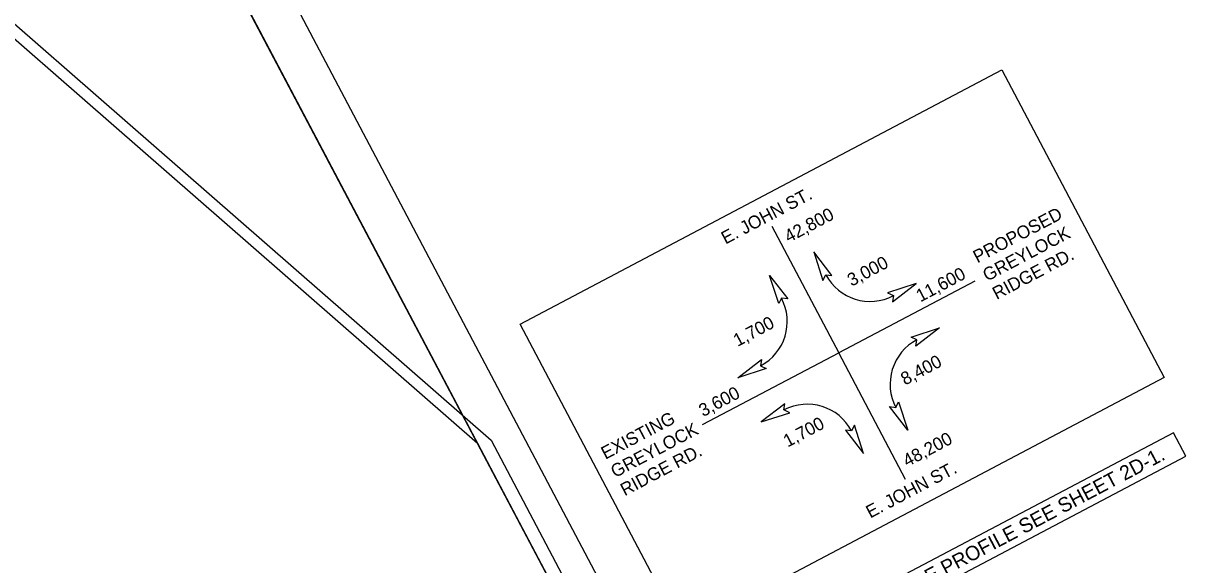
# Model space of a CAD drawing. Extents: x 1487051 to 1489241, y 497582 to 499399.
# Drawn here: x 1488789 to 1489240.5, y 498446.4 to 498656.8 of the extents above; entities that cross this region are included whole.
import ezdxf

# ---------------------------------------------------------------- set-up
doc = ezdxf.new("R2010")
doc.units = 0
for name, color, linetype in [('COGO Default Point Elevation', 7, 'Continuous'), ('Exist DTM Regular Point Cogo Elevation', 7, 'Continuous'), ('Exist Other Culture Sign Post Cogo Comment', 7, 'Continuous'), ('Exist Other Culture Sign Post Cogo Number', 7, 'Continuous'), ('Exist Roads EOP Cogo Point CELL', 7, 'Continuous'), ('Exist Structure Minor Pipes RCP 15 Inch Cogo Comment', 7, 'Continuous'), ('Exist Vegetation Woods Line Cogo Elevation', 7, 'Continuous')]:
    doc.layers.add(name, color=color, linetype=linetype)

msp = doc.modelspace()

# ---------------------------------------------------------------- linework, layer by layer
at = {"layer": 'Exist DTM Regular Point Cogo Elevation'}
for points in [[(1487208.66, 498608.09), (1488222.07, 499143.23), (1488965.37, 498493.68), (1489025.39, 498380), (1487698.94, 497679.61)], [(1487208.66, 498608.09), (1488222.07, 499143.23), (1488965.37, 498493.68), (1489025.39, 498380), (1487698.94, 497679.61)], [(1487214.01, 498609.18), (1488227.42, 499144.32), (1488970.72, 498494.78), (1489030.74, 498381.1), (1487704.3, 497680.71)]]:
    msp.add_lwpolyline(points, close=True, dxfattribs=at)
at = {"layer": 'Exist Other Culture Sign Post Cogo Comment'}
msp.add_lwpolyline([(1488264.23, 499106.38), (1488223.12, 499143.79), (1487208.65, 498608.11), (1487698.94, 497679.61), (1489025.4, 498380.01), (1488871.95, 498670.61), (1488744.3, 498686.86)], close=True, dxfattribs=at)
at = {"layer": 'Exist Other Culture Sign Post Cogo Number'}
for p in [(1489079.72, 498577.99), (1489158.54, 498556.66), (1489052.88, 498500.87), (1489131.7, 498479.55)]:
    msp.add_line(p, (1489105.71, 498528.77), dxfattribs=at)
for points in [[(1489103.08, 498558.78), (1489096.02, 498567.94), (1489099.58, 498556.87), (1489100.69, 498559.1)], [(1489082.41, 498547.87), (1489078.83, 498558.86), (1489085.97, 498549.68), (1489083.5, 498550.02)], [(1489126.65, 498548.6), (1489135.81, 498555.65), (1489124.73, 498552.09), (1489126.96, 498550.98)], [(1489133.9, 498534.87), (1489144.89, 498538.46), (1489135.7, 498531.32), (1489136.04, 498533.79)], [(1489077.53, 498522.66), (1489066.54, 498519.08), (1489075.72, 498526.22), (1489075.38, 498523.75)], [(1489129.01, 498509.66), (1489132.6, 498498.67), (1489125.46, 498507.86), (1489127.93, 498507.51)], [(1489084.77, 498508.94), (1489075.62, 498501.88), (1489086.69, 498505.44), (1489084.46, 498506.55)], [(1489108.35, 498498.75), (1489115.4, 498489.59), (1489111.84, 498500.67), (1489110.73, 498498.44)]]:
    msp.add_lwpolyline(points, close=True, dxfattribs=at)
for centre, start, end in [((1489117.89, 498568.18), 207.8351, 297.8351), ((1489066.3, 498540.94), 297.8351, 27.8351), ((1489145.12, 498516.59), 117.8351, 207.8351), ((1489093.54, 498489.36), 27.8351, 117.8351)]:
    msp.add_arc(centre, 19.44, start, end, dxfattribs=at)
at = {"layer": 'Exist Roads EOP Cogo Point CELL'}
msp.add_lwpolyline([(1487562.23, 497581.96), (1489050.94, 498368.04), (1488539.66, 499336.34), (1487050.94, 498550.27)], close=True, dxfattribs=at)
at = {"layer": 'Exist Structure Minor Pipes RCP 15 Inch Cogo Comment'}
for points in [[(1488535.14, 499308.53), (1487208.67, 498608.12), (1487698.94, 497679.61), (1489025.4, 498380.01)], [(1487698.94, 497679.61), (1487208.66, 498608.09), (1488358.21, 499215.12), (1488375.74, 499181.9), (1488552.62, 499275.32), (1489025.4, 498380.01)]]:
    msp.add_lwpolyline(points, close=True, dxfattribs=at)
at = {"layer": 'Exist Vegetation Woods Line Cogo Elevation'}
for points in [[(1488981.95, 498539.84), (1489169.07, 498638.65), (1489232.18, 498519.12), (1489045.06, 498420.32)], [(1489112.71, 498421.06), (1489240.52, 498488.55), (1489235.71, 498497.67), (1489107.89, 498430.18)]]:
    msp.add_lwpolyline(points, close=True, dxfattribs=at)

# ---------------------------------------------------------------- texts
at = {"layer": 'COGO Default Point Elevation'}
msp.add_text('FOR PIPE PROFILE SEE SHEET 2D-1.', height=5.625, rotation=27.8351, dxfattribs=at).set_placement((1489114.34, 498424.87))
at = {"layer": 'Exist Other Culture Sign Post Cogo Number'}
for s, p in [('E. JOHN ST.', (1489061.76, 498570.8)), ('42,800', (1489086.3, 498571.41)), ('PROPOSED', (1489159.59, 498563.48)), ('GREYLOCK', (1489163.35, 498556.37)), ('3,000', (1489110.73, 498554.41)), ('RIDGE RD.', (1489167.1, 498549.26)), ('11,600', (1489137.45, 498548.32)), ('1,700', (1489066.43, 498531.02)), ('8,400', (1489131.49, 498516)), ('3,600', (1489053.05, 498503.75)), ('EXISTING', (1489015.1, 498487.19)), ('GREYLOCK', (1489018.85, 498480.08)), ('1,700', (1489085.88, 498491.92)), ('48,200', (1489132.31, 498484.27)), ('RIDGE RD.', (1489022.61, 498472.97)), ('E. JOHN ST.', (1489117.97, 498464.35))]:
    msp.add_text(s, height=5, rotation=27.8351, dxfattribs=at).set_placement(p)

doc.saveas('drawing.dxf')
